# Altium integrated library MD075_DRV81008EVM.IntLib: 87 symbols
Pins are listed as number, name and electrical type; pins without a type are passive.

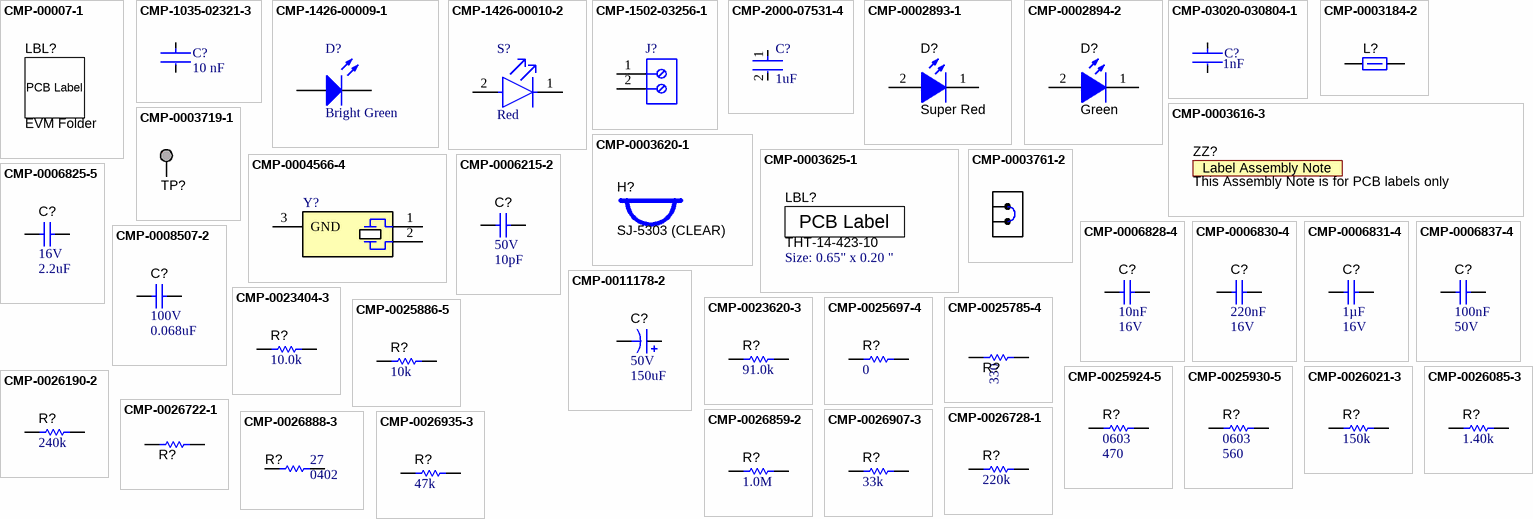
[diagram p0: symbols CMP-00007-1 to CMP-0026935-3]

## CMP-00007-1
designator LBL?, comment EVM Folder
Harsh Environment Multi-Purpose Polyester Labels for 3" Core Printers - 0.375" x 0.375", White; Manufacturer: Brady; PartNumber: THT-14-423-10; CompType: Label; Body Material: PET,Polyester; Note: Size: 0.375" x 0.375"
footprint Label_375x375 (Thermal Transfer Label)

## CMP-1035-02321-3
designator C?, comment value 10 nF  (hidden comment: CC0603KPX7R9BB103)
CAP CER 10000PF 50V X7R 0603; Manufacturer: YAGEO; Alternative PartNumber: 885382206002; Alternative Manufacturer: Wurth Elektronik; Tolerance: 0.1; Material: Ceramic; Temperature Coefficient: 15%
footprint FP-CC0603-DA-MFG
footprint FP-CC0603-DA-IPC_C
footprint FP-CC0603-DA-IPC_B
footprint FP-CC0603-DA-IPC_A
pins: 1, 2

## CMP-1426-00009-1
designator D?, comment Color: Bright Green  (hidden comment: 150080VS75000)
SMD mono-color Chip LED, WL-SMCW, Bright Green; Manufacturer: Wuerth Elektronik
footprint 0805_A (Chip LED, 2-Leads, Body 2.0x1.3mm, IPC Medium Density)
pins: 1 K, 2 A

## CMP-1426-00010-2
designator S?, comment Color: Red  (hidden comment: 150080SS75000)
LED RED CLEAR 0805 SMD; Forward Voltage: 1.9V; Luminous Intensity: 60mcd; Dominant Wavelength: 630nm; Forward Current: 30mA; Viewing Angle: 140°; Lens Color: Colorless; Test Current: 20mA; Lens Size: 1.25mm
footprint FP-150080SS75000-MFG
pins: 1 C, 2 A

## CMP-1502-03256-1
designator J?, comment 691101710002  (value not drawn)
Series 101 - 5.00 mm Horizontal Entry Modular with Pressure Clamp WR-TBL, 2 pin; Manufacturer: Wurth Elektronik; Pin Number: 2; Pitch: 5.00mm
footprint 691101710002 (5,00mm - modular - blue - Horizontal entry with pressure clamp - 12,6mm height - 02p)
pins: 1, 2

## CMP-2000-07531-4
designator C?, comment Capacitance: 1uF  (hidden comment: UMK107AB7105KA-T)
Ceramic Capacitor General Use 1uF ±10% 50V X7R 0603
footprint FP-0603-L_1_6_0_15-W_0_8-IPC_C
footprint FP-0603-L_1_6_0_15-W_0_8-MFG
footprint FP-0603-L_1_6_0_15-W_0_8-IPC_A
footprint FP-0603-L_1_6_0_15-W_0_8-IPC_B
pins: 1, 2

## CMP-0002893-1
designator D?, comment value Super Red  (hidden comment: 150060SS75000)
LED, Super Red, SMD; Manufacturer: Wurth Elektronik; Io_A: 20mA; Value1: W; U/M: EA; Vf_V: 1.9V; Type: AlInGaP
footprint WL-SMCW_RED (WURTH)
pins: 1 K, 2 A

## CMP-0002894-2
designator D?, comment value Green  (hidden comment: 150060VS75000)
LED, Green, SMD; Manufacturer: Wurth Elektronik; Type: AlInGaP; Vf_V: 2V; Io_A: 20mA; Value1: W
footprint WL-SMCW_GREEN (WURTH)
pins: 1 K, 2 A

## CMP-03020-030804-1
designator C?, comment 1nF
CAP CER 1000PF 50V X7R 0603; Manufacturer Part Number: C0603C102J5RACAUTO; Manufacturer: KEMET; Alternate PartNumber: 885012206083; Alternate Manufacturer: Wurth Elektronik; Material: Ceramic; Value: 1,000 pF; Temperature Coefficient: 30ppm/°C; Automotive Grade: Grade 1; Tolerance: 0.05
footprint FP-C0603C-CF-MFG
footprint FP-C0603C-CF-IPC_C
footprint FP-C0603C-CF-IPC_B
footprint FP-C0603C-CF-IPC_A
pins: 1, 2

## CMP-0003184-2
designator L?, comment 742792621  (value not drawn)
Ferrite Bead, 140 ohm @ 100 MHz, 0.55 A, 0603; Manufacturer: Wurth Elektronik; Ztyp@1GHz_Ohm: 271.401; ZTyp@100MHz_Ohm: 140; SizeAreaWB_mm2: 4.68; DCR_ohm: 0.2; Value1: 0.2 ohm; Value: 140 ohm; Imax_A: 550mA; SizeZ_mm: 1; SizeX_mm: 1.6; SizeY_mm: 0.8; Value2: 0.55A; SizeArea_mm2: 1.28
footprint 0603 (0603 from SM-752 data)
footprint 0603_HV (Ernesto recommended land pattern.  26 mil between pads.)
footprint 0603L (0603 from SM-752 data)
footprint 0603S
footprint 0603M (0603 from SM-752 data)
pins: 1, 2

## CMP-0003616-3
designator ZZ?, comment This Assembly Note is for PCB labels only  (no BOM)
Key: AssemblyNoteLabel
footprint AssemblyNoteLabel (Assembly Note for PCB Labels)

## CMP-0003620-1
designator H?, comment SJ-5303 (CLEAR)
Bumpon, Hemisphere, 0.44 X 0.20, Clear; Manufacturer: 3M
footprint Bumpon_SJ5003Transparent (3M Hemispherical Bumpon transparent)

## CMP-0003625-1
designator LBL?, comment THT-14-423-10  Note: Size: 0.65" x 0.20 "
Thermal Transfer Printable Labels, 0.650" W x 0.200" H - 10,000 per roll; Manufacturer: Brady; CompType: Label
footprint Label_650x200 (Thermal Transfer Label)

## CMP-0003719-1
designator TP?, comment TP_H0.45P0.75  (value not drawn)  (no BOM)
Testpoint; Manufacturer: Texas Instruments; CompType: Pad
footprint TP_H045P075 (TP_H0.45P0.75)
pins: 1

## CMP-0003761-2
designator SH-J?, comment 60900213421  (value not drawn)
Shunt, 2.54mm, Gold, Black; Manufacturer: Wurth Elektronik
footprint Wurth_60900213421 (Shunt, 2.54mm, Black)

## CMP-0004566-4
designator Y?, comment MS3V-T1R 32.768KHZ +/-20PPM 12.5PF  (value not drawn)
Crystal, 32.768 kHz, 12.5pF, SMD; Manufacturer: Micro Crystal AG; TaMin_C: -40°C; TaMax_C: 85°C; AEC Category: Q200; AEC Qualified: N; Frequency Tolerance: 20 ppm
footprint XTAL_MS3V-T1R (Micro Crystal Switzerland recommended land pattern)
pins: 1, 2, 3 GND (power)

## CMP-0006215-2
designator C?, comment VDC_V: 50V  ValueDisplayed: 10pF  (hidden comment: 885012005055)
CAP, CERM, 10 pF, 50 V, +/- 5%, C0G/NP0, 0402; Manufacturer: Wurth Elektronik; TaMin_C: -55°C; Polarized: N; SizeAreaWB_mm2: 3; Value1: Unknown; U/M: EA; Value: 10pF; TaMax_C: 125°C; SizeZ_mm: 0.6; SizeX_mm: 1; SizeY_mm: 0.5; Cap_Case: 0402; CompType: Capacitor; AEC Category: Q200
footprint 0402 (0402 from SM-752 data)
footprint 0402S (Based on C0402S footprint from PADS legacy)
footprint 0402L (0402 from SM-752 data)
footprint 0402M (0402 from SM-752 data)
pins: 1, 2

## CMP-0006825-5
designator C?, comment VDC_V: 16V  ValueDisplayed: 2.2uF  (hidden comment: 885012106018)
CAP, CERM, 2.2 uF, 16 V, +/- 20%, X5R, 0603; Manufacturer: Wurth Elektronik; TaMin_C: -55°C; Polarized: N; SizeAreaWB_mm2: 4.68; Value1: Unknown; U/M: EA; Value: 2.2uF; TaMax_C: 85°C; SizeZ_mm: 1; SizeX_mm: 1.6; SizeY_mm: 0.8; Cap_Case: 0603; SizeArea_mm2: 1.28; CompType: Capacitor; Cap_F: 2.2µF; AEC Category: Q200
footprint 0603 (0603 from SM-752 data)
footprint 0603_HV (Ernesto recommended land pattern.  26 mil between pads.)
footprint 0603L (0603 from SM-752 data)
footprint 0603S
footprint 0603M (0603 from SM-752 data)
pins: 1, 2

## CMP-0006828-4
designator C?, comment Cap_F: 10nF  VDC_V: 16V  (hidden comment: 885012206040)
CAP, CERM, 0.01 uF, 16 V, +/- 10%, X7R, 0603; Manufacturer: Wurth Elektronik; TaMin_C: -55°C; Polarized: N; SizeAreaWB_mm2: 4.68; Value1: Unknown; U/M: EA; Value: 0.01uF; TaMax_C: 125°C; SizeZ_mm: 1; SizeX_mm: 1.6; SizeY_mm: 0.8; Cap_Case: 0603; SizeArea_mm2: 1.28; CompType: Capacitor; AEC Category: Q200
footprint 0603 (0603 from SM-752 data)
footprint 0603_HV (Ernesto recommended land pattern.  26 mil between pads.)
footprint 0603L (0603 from SM-752 data)
footprint 0603S
footprint 0603M (0603 from SM-752 data)
pins: 1, 2

## CMP-0006830-4
designator C?, comment Cap_F: 220nF  VDC_V: 16V  (hidden comment: 885012206048)
CAP, CERM, 0.22 uF, 16 V, +/- 10%, X7R, 0603; Manufacturer: Wurth Elektronik; TaMin_C: -55°C; Polarized: N; SizeAreaWB_mm2: 4.68; Value1: Unknown; U/M: EA; Value: 0.22uF; TaMax_C: 125°C; SizeZ_mm: 1; SizeX_mm: 1.6; SizeY_mm: 0.8; Cap_Case: 0603; SizeArea_mm2: 1.28; CompType: Capacitor; AEC Category: Q200
footprint 0603 (0603 from SM-752 data)
footprint 0603_HV (Ernesto recommended land pattern.  26 mil between pads.)
footprint 0603L (0603 from SM-752 data)
footprint 0603S
footprint 0603M (0603 from SM-752 data)
pins: 1, 2

## CMP-0006831-4
designator C?, comment Cap_F: 1µF  VDC_V: 16V  (hidden comment: 885012206052)
CAP, CERM, 1 uF, 16 V, +/- 10%, X7R, 0603; Manufacturer: Wurth Elektronik; TaMin_C: -55°C; Polarized: N; SizeAreaWB_mm2: 4.68; Value1: Unknown; U/M: EA; Value: 1uF; TaMax_C: 125°C; SizeZ_mm: 1; SizeX_mm: 1.6; SizeY_mm: 0.8; Cap_Case: 0603; SizeArea_mm2: 1.28; CompType: Capacitor; AEC Category: Q200
footprint 0603 (0603 from SM-752 data)
footprint 0603_HV (Ernesto recommended land pattern.  26 mil between pads.)
footprint 0603L (0603 from SM-752 data)
footprint 0603S
footprint 0603M (0603 from SM-752 data)
pins: 1, 2

## CMP-0006837-4
designator C?, comment Cap_F: 100nF  VDC_V: 50V  (hidden comment: 885012206095)
CAP, CERM, 0.1 uF, 50 V, +/- 10%, X7R, 0603; Manufacturer: Wurth Elektronik; TaMin_C: -55°C; Polarized: N; SizeAreaWB_mm2: 4.68; Value1: Unknown; U/M: EA; Value: 0.1uF; TaMax_C: 125°C; SizeZ_mm: 1; SizeX_mm: 1.6; SizeY_mm: 0.8; Cap_Case: 0603; SizeArea_mm2: 1.28; CompType: Capacitor; AEC Category: Q200
footprint 0603 (0603 from SM-752 data)
footprint 0603_HV (Ernesto recommended land pattern.  26 mil between pads.)
footprint 0603L (0603 from SM-752 data)
footprint 0603S
footprint 0603M (0603 from SM-752 data)
pins: 1, 2

## CMP-0008507-2
designator C?, comment VDC_V: 100V  ValueDisplayed: 0.068uF  (hidden comment: 12061C683KAT2A)
CAP, CERM, 0.068 uF, 100 V, +/- 10%, X7R, 1206; Manufacturer: AVX; TaMin_C: -55°C; ESR_ohm: 0.045; Polarized: N; SizeAreaWB_mm2: 10.92; Value1: 0.045 ohm; U/M: EA; TaMax_C: 125°C; SizeZ_mm: 1.35; SizeX_mm: 3.2; SizeY_mm: 1.6; Cap_Case: 1206; SizeArea_mm2: 5.12; CompType: Capacitor; Cap_F: 68nF; AEC Category: Q200
footprint 1206 (1206 from SM-752 data)
footprint 1206L (1206 from SM-752 data)
footprint 1206M (1206 from SM-752 data)
pins: 1, 2

## CMP-0011178-2
designator C?, comment VDC_V: 50V  ValueDisplayed: 150uF  (hidden comment: EEE-FK1H151P)
CAP, AL, 150 uF, 50 V, +/- 20%, 0.18 ohm, AEC-Q200 Grade 2, SMD; Manufacturer: Panasonic; Alternate Manufacturer: Wurth Elektronik; Alternate PartNumber: 865080657017; TaMin_C: -55°C; ESR_ohm: 0.18; Polarized: Y; SizeAreaWB_mm2: 172.2; U/M: EA; Value: 150uF; TaMax_C: 105°C; SizeZ_mm: 10.2; SizeX_mm: 12; SizeY_mm: 10.3; Cap_Case: G; SizeArea_mm2: 123.6; CompType: Capacitor; Cap_F: 150µF; IRMS_A: 670mA; AEC Grade: 2; AEC Category: Q200
footprint SM_RADIAL_G (10 x 10.2mm:  Panasonic G)
pins: 1 +, 2 -

## CMP-0023404-3
designator R?, comment ValueDisplayed: 10.0k  (hidden comment: RG1608P-103-B-T5)
RES, 10.0 k, 0.1%, 0.1 W, 0603; Manufacturer: Susumu Co Ltd; Power_W: 100mW; TempCo: 25 ppm/C; Value_Code: 10k0; U/M: EA; Value: 10.0k; EIA_Code: E192; Res_ohm: 10k; SizeX_mm: 1.6; SizeY_mm: 0.8; SizeZ_mm: 1; Value2: 0.1W; SizeArea_mm2: 1.28; CompType: Resistor; VDC_V: 75V; AEC Category: Q200
footprint 0603 (0603 from SM-752 data)
footprint 0603_HV (Ernesto recommended land pattern.  26 mil between pads.)
footprint 0603L (0603 from SM-752 data)
footprint 0603S
footprint 0603M (0603 from SM-752 data)
pins: 1, 2

## CMP-0023620-3
designator R?, comment ValueDisplayed: 91.0k  (hidden comment: RG1608P-913-B-T5)
RES, 91.0 k, 0.1%, 0.1 W, 0603; Manufacturer: Susumu Co Ltd; Power_W: 100mW; TempCo: 25 ppm/C; Value_Code: 91k0; U/M: EA; Value: 91.0k; Res_ohm: 91k; SizeX_mm: 1.6; SizeY_mm: 0.8; SizeZ_mm: 1; Value2: 0.1W; SizeArea_mm2: 1.28; CompType: Resistor; VDC_V: 75V; AEC Category: Q200
footprint 0603 (0603 from SM-752 data)
footprint 0603_HV (Ernesto recommended land pattern.  26 mil between pads.)
footprint 0603L (0603 from SM-752 data)
footprint 0603S
footprint 0603M (0603 from SM-752 data)
pins: 1, 2

## CMP-0025697-4
designator R?, comment value 0  (hidden comment: Resistor)
RES, 0, 5%, 0.1 W, AEC-Q200 Grade 0, 0603; PartNumber: CRCW06030000Z0EA; Manufacturer: Vishay-Dale; Value_Code: 0000; Power_W: 100mW; Value2: 0.1W; VDC_V: 75V; TempCo: 200 ppm/C; EIA_Code: E24; AEC Category: Q200; AEC Qualified: Y; SizeArea_mm2: 1.28; SizeX_mm: 1.6; SizeY_mm: 0.8; SizeZ_mm: 1
footprint 0603 (0603 from SM-752 data)
footprint 0603_HV (Ernesto recommended land pattern.  26 mil between pads.)
footprint 0603L (0603 from SM-752 data)
footprint 0603S
footprint 0603M (0603 from SM-752 data)
pins: 1, 2

## CMP-0025785-4
designator R?, comment ValueDisplayed: 330  (hidden comment: Resistor)
RES, 330, 5%, 0.1 W, AEC-Q200 Grade 0, 0603; PartNumber: CRCW0603330RJNEA; Manufacturer: Vishay-Dale; Value: 330; Value_Code: 330R; Power_W: 100mW; Value2: 0.1W; VDC_V: 75V; TempCo: 200 ppm/C; EIA_Code: E24; AEC Category: Q200; AEC Qualified: Y; AEC Grade: 0; SizeX_mm: 1.6; SizeY_mm: 0.8; SizeZ_mm: 1; SizeArea_mm2: 1.28
footprint 0603 (0603 from SM-752 data)
footprint 0603_HV (Ernesto recommended land pattern.  26 mil between pads.)
footprint 0603L (0603 from SM-752 data)
footprint 0603S
footprint 0603M (0603 from SM-752 data)
pins: 1, 2

## CMP-0025886-5
designator R?, comment ValueDisplayed: 10k  (hidden comment: RC0603JR-0710KL)
RES, 10 k, 5%, 0.1 W, 0603; Manufacturer: Yageo; Power_W: 100mW; TempCo: 100 ppm/C; Value_Code: 10k0; Value: 10k; EIA_Code: E24; SizeX_mm: 1.6; SizeY_mm: 0.8; SizeZ_mm: 1; Value2: 0.1W; SizeArea_mm2: 1.28; CompType: Resistor; AEC Qualified: N; VDC_V: 75V; AEC Category: Q200; SizeAreaWB_mm2: 4.68
footprint 0603 (0603 from SM-752 data)
footprint 0603_HV (Ernesto recommended land pattern.  26 mil between pads.)
footprint 0603L (0603 from SM-752 data)
footprint 0603S
footprint 0603M (0603 from SM-752 data)
pins: 1, 2

## CMP-0025924-5
designator R?, comment PackageReference: 0603  ValueDisplayed: 470  (hidden comment: RC0603JR-07470RL)
RES, 470, 5%, 0.1 W, 0603; Manufacturer: Yageo; Power_W: 100mW; TempCo: 100 ppm/C; Value_Code: 470R; Value: 470; EIA_Code: E24; SizeX_mm: 1.6; SizeY_mm: 0.8; SizeZ_mm: 1; Value2: 0.1W; SizeArea_mm2: 1.28; CompType: Resistor; AEC Qualified: N; VDC_V: 75V; AEC Category: Q200; SizeAreaWB_mm2: 4.68
footprint 0603 (0603 from SM-752 data)
footprint 0603_HV (Ernesto recommended land pattern.  26 mil between pads.)
footprint 0603L (0603 from SM-752 data)
footprint 0603S
footprint 0603M (0603 from SM-752 data)
pins: 1, 2

## CMP-0025930-5
designator R?, comment PackageReference: 0603  ValueDisplayed: 560  (hidden comment: RC0603JR-07560RL)
RES, 560, 5%, 0.1 W, 0603; Manufacturer: Yageo; Power_W: 100mW; TempCo: 100 ppm/C; Value_Code: 560R; Value: 560; EIA_Code: E24; SizeX_mm: 1.6; SizeY_mm: 0.8; SizeZ_mm: 1; Value2: 0.1W; SizeArea_mm2: 1.28; CompType: Resistor; AEC Qualified: N; VDC_V: 75V; AEC Category: Q200; SizeAreaWB_mm2: 4.68
footprint 0603 (0603 from SM-752 data)
footprint 0603_HV (Ernesto recommended land pattern.  26 mil between pads.)
footprint 0603L (0603 from SM-752 data)
footprint 0603S
footprint 0603M (0603 from SM-752 data)
pins: 1, 2

## CMP-0026021-3
designator R?, comment ValueDisplayed: 150k  (hidden comment: CRCW0402150KFKED)
RES, 150 k, 1%, 0.063 W, AEC-Q200 Grade 0, 0402; Manufacturer: Vishay-Dale; Power_W: 63mW; TempCo: 100 ppm/C; Value: 150k; EIA_Code: E96; SizeX_mm: 1; SizeY_mm: 0.5; SizeZ_mm: 0.6; Value2: 0.063W; CompType: Resistor; AEC Qualified: Y; VDC_V: 50V; AEC Category: Q200; AEC Grade: 0
footprint 0402 (0402 from SM-752 data)
footprint 0402S (Based on C0402S footprint from PADS legacy)
footprint 0402L (0402 from SM-752 data)
footprint 0402M (0402 from SM-752 data)
pins: 1, 2

## CMP-0026085-3
designator R?, comment ValueDisplayed: 1.40k  (hidden comment: CRCW04021K40FKED)
RES, 1.40 k, 1%, 0.063 W, AEC-Q200 Grade 0, 0402; Manufacturer: Vishay-Dale; Power_W: 63mW; TempCo: 100 ppm/C; Value_Code: 1k40; Value: 1.40k; EIA_Code: E96; Res_ohm: 1.4k; SizeX_mm: 1; SizeY_mm: 0.5; SizeZ_mm: 0.6; Value2: 0.063W; CompType: Resistor; AEC Qualified: Y; VDC_V: 50V; AEC Category: Q200; AEC Grade: 0
footprint 0402 (0402 from SM-752 data)
footprint 0402S (Based on C0402S footprint from PADS legacy)
footprint 0402L (0402 from SM-752 data)
footprint 0402M (0402 from SM-752 data)
pins: 1, 2

## CMP-0026190-2
designator R?, comment ValueDisplayed: 240k  (hidden comment: CRCW0402240KFKED)
RES, 240 k, 1%, 0.063 W, AEC-Q200 Grade 0, 0402; Manufacturer: Vishay-Dale; Power_W: 63mW; TempCo: 100 ppm/C; Value: 240k; SizeX_mm: 1; SizeY_mm: 0.5; SizeZ_mm: 0.6; Value2: 0.063W; CompType: Resistor; AEC Qualified: Y; VDC_V: 50V; AEC Category: Q200; AEC Grade: 0
footprint 0402 (0402 from SM-752 data)
footprint 0402S (Based on C0402S footprint from PADS legacy)
footprint 0402L (0402 from SM-752 data)
footprint 0402M (0402 from SM-752 data)
pins: 1, 2

## CMP-0026722-1
designator R?, comment RC0402FR-07100RL  (value not drawn)
RES, 100, 1%, 0.063 W, 0402; Manufacturer: Yageo America; Power_W: 63mW; TempCo: 100 ppm/C; Value_Code: 100R; U/M: EA; Value: 100; EIA_Code: E96; SizeX_mm: 1; SizeY_mm: 0.5; SizeZ_mm: 0.6; Value2: 0.063W; CompType: Resistor; AEC Qualified: N; VDC_V: 50V; AEC Category: Q200
footprint 0402 (0402 from SM-752 data)
footprint 0402S (Based on C0402S footprint from PADS legacy)
footprint 0402L (0402 from SM-752 data)
footprint 0402M (0402 from SM-752 data)
pins: 1, 2

## CMP-0026728-1
designator R?, comment ValueDisplayed: 220k  (hidden comment: RC0402FR-07220KL)
RES, 220 k, 1%, 0.0625 W, 0402; Manufacturer: Yageo America; Power_W: 62.5mW; TempCo: 100 ppm/C; U/M: EA; Value: 220k; SizeX_mm: 1; SizeY_mm: 0.5; SizeZ_mm: 0.6; CompType: Resistor; AEC Qualified: N; VDC_V: 50V; AEC Category: Q200
footprint 0402 (0402 from SM-752 data)
footprint 0402S (Based on C0402S footprint from PADS legacy)
footprint 0402L (0402 from SM-752 data)
footprint 0402M (0402 from SM-752 data)
pins: 1, 2

## CMP-0026859-2
designator R?, comment ValueDisplayed: 1.0M  (hidden comment: CRCW04021M00JNED)
RES, 1.0 M, 5%, 0.063 W, AEC-Q200 Grade 0, 0402; Manufacturer: Vishay-Dale; Power_W: 63mW; TempCo: 200 ppm/C; Value_Code: 1M00; Value: 1.0Meg; EIA_Code: E24; Res_ohm: 1M; SizeX_mm: 1; SizeY_mm: 0.5; SizeZ_mm: 0.6; Value2: 0.063W; CompType: Resistor; AEC Qualified: Y; VDC_V: 50V; AEC Category: Q200; AEC Grade: 0
footprint 0402 (0402 from SM-752 data)
footprint 0402S (Based on C0402S footprint from PADS legacy)
footprint 0402L (0402 from SM-752 data)
footprint 0402M (0402 from SM-752 data)
pins: 1, 2

## CMP-0026888-3
designator R?, comment PackageReference: 0402  ValueDisplayed: 27  (hidden comment: CRCW040227R0JNED)
RES, 27, 5%, 0.063 W, AEC-Q200 Grade 0, 0402; Manufacturer: Vishay-Dale; Power_W: 63mW; TempCo: 200 ppm/C; Value_Code: 27R0; Value: 27; EIA_Code: E24; SizeX_mm: 1; SizeY_mm: 0.5; SizeZ_mm: 0.6; Value2: 0.063W; CompType: Resistor; AEC Qualified: Y; VDC_V: 50V; AEC Category: Q200; AEC Grade: 0
footprint 0402 (0402 from SM-752 data)
footprint 0402S (Based on C0402S footprint from PADS legacy)
footprint 0402L (0402 from SM-752 data)
footprint 0402M (0402 from SM-752 data)
pins: 1, 2

## CMP-0026907-3
designator R?, comment ValueDisplayed: 33k  (hidden comment: CRCW040233K0JNED)
RES, 33 k, 5%, 0.063 W, AEC-Q200 Grade 0, 0402; Manufacturer: Vishay-Dale; Power_W: 63mW; TempCo: 200 ppm/C; Value_Code: 33k0; Value: 33k; EIA_Code: E24; SizeX_mm: 1; SizeY_mm: 0.5; SizeZ_mm: 0.6; Value2: 0.063W; CompType: Resistor; AEC Qualified: Y; VDC_V: 50V; AEC Category: Q200; AEC Grade: 0
footprint 0402 (0402 from SM-752 data)
footprint 0402S (Based on C0402S footprint from PADS legacy)
footprint 0402L (0402 from SM-752 data)
footprint 0402M (0402 from SM-752 data)
pins: 1, 2

## CMP-0026935-3
designator R?, comment ValueDisplayed: 47k  (hidden comment: CRCW040247K0JNED)
RES, 47 k, 5%, 0.063 W, AEC-Q200 Grade 0, 0402; Manufacturer: Vishay-Dale; Power_W: 63mW; TempCo: 200 ppm/C; Value_Code: 47k0; Value: 47k; EIA_Code: E24; SizeX_mm: 1; SizeY_mm: 0.5; SizeZ_mm: 0.6; Value2: 0.063W; CompType: Resistor; AEC Qualified: Y; VDC_V: 50V; AEC Category: Q200; AEC Grade: 0
footprint 0402 (0402 from SM-752 data)
footprint 0402S (Based on C0402S footprint from PADS legacy)
footprint 0402L (0402 from SM-752 data)
footprint 0402M (0402 from SM-752 data)
pins: 1, 2

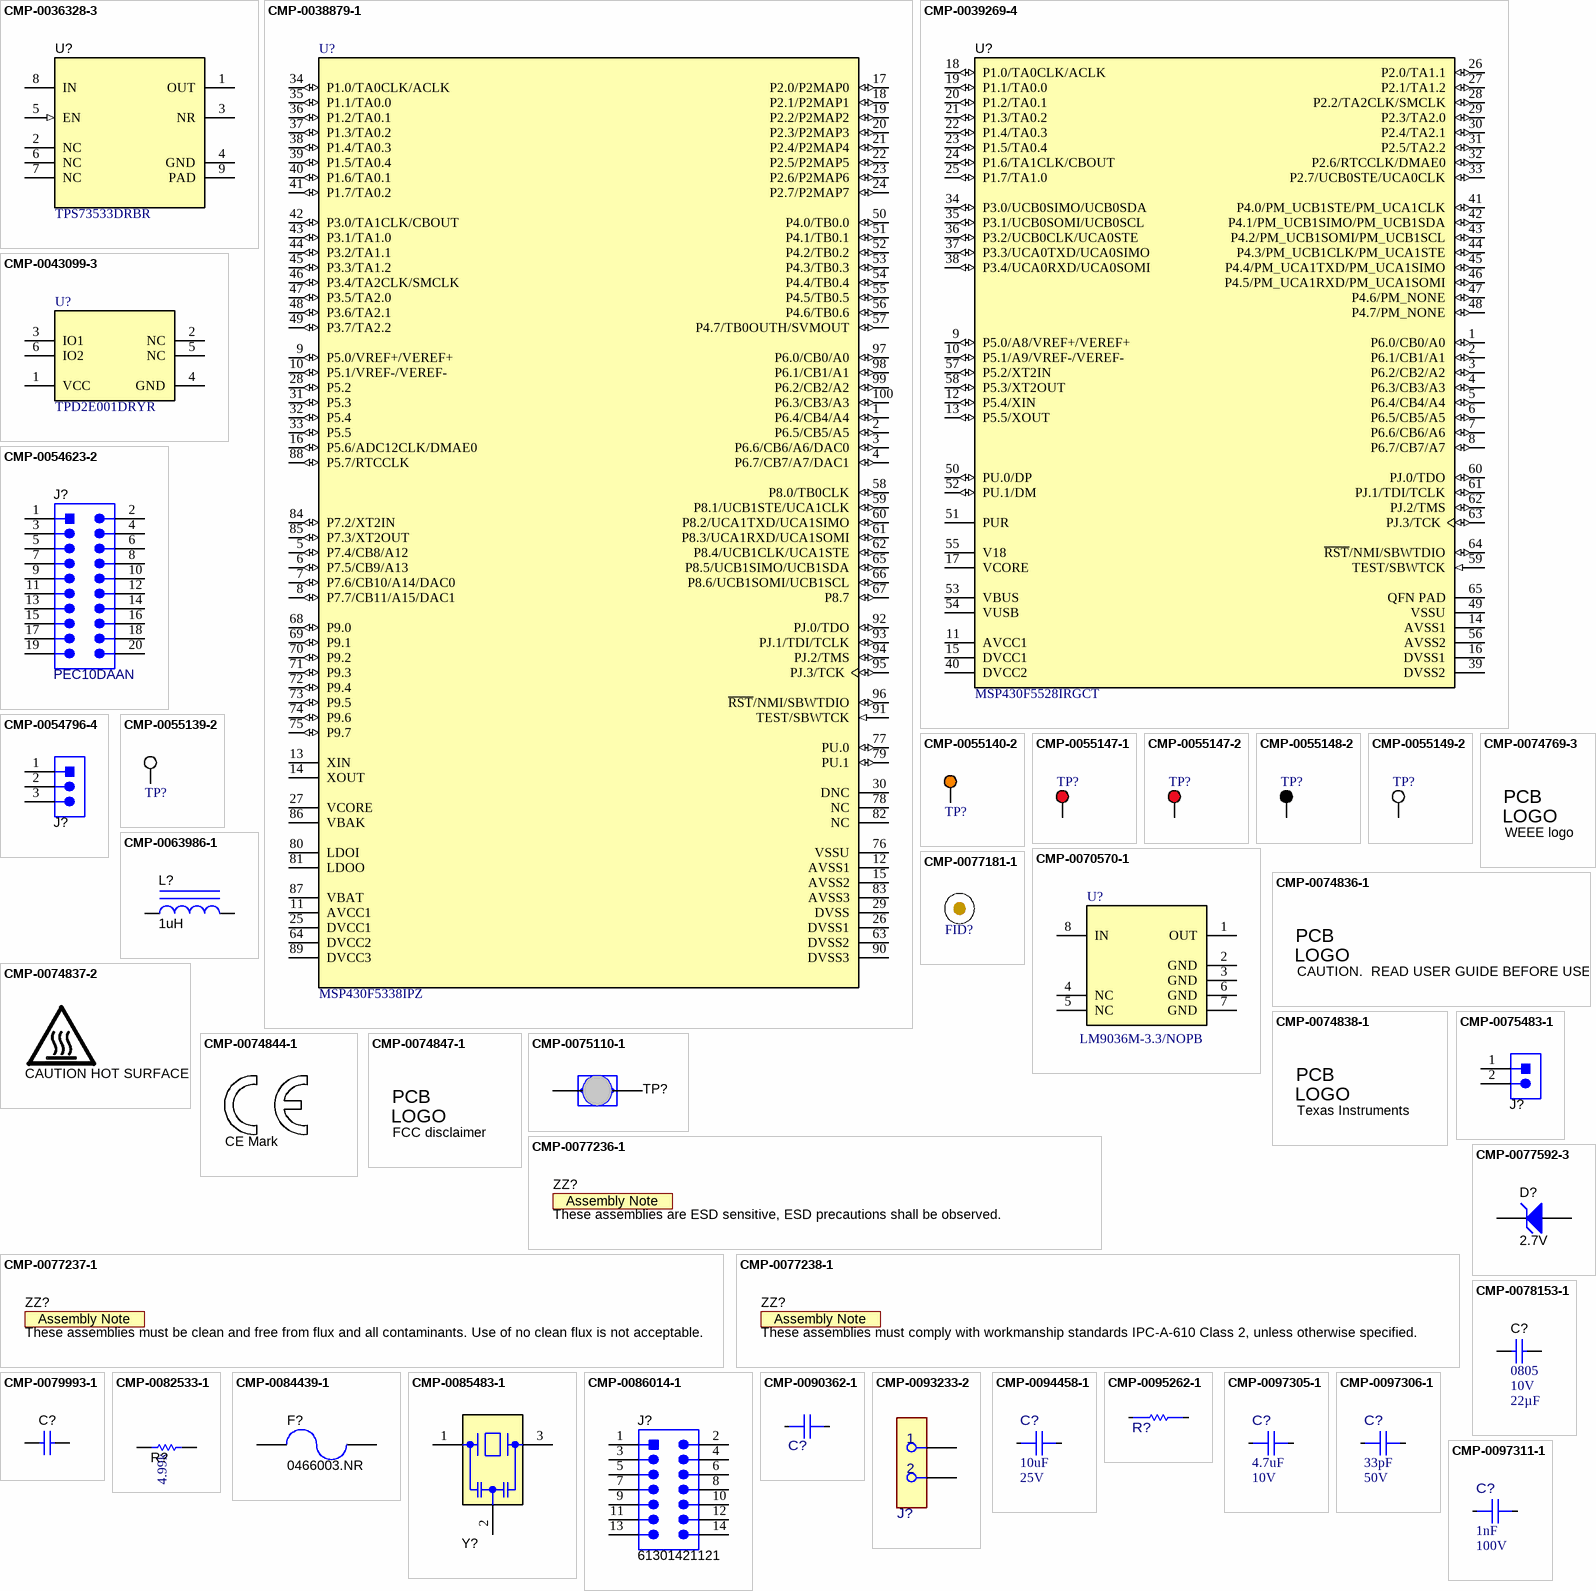
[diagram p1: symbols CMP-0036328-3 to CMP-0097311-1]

## CMP-0036328-3
designator U?, comment TPS73533DRBR
500mA, Adjustable, Low Quiescent Current, Low-Noise, High-PSRR, Single-Output LDO Regulator, DRB0008A (VSON-8); Manufacturer: Texas Instruments; CompType: IC; Green_Lifecycle: Active; SizeZ_mm: 1.0; Iq(Typ)(mA): 0.04; SizeY_mm: 3.0; SizeAreaWB_mm2: 16.0; SizeArea_mm2: 9.0; AEC Category: Q200; Vout Adj(Max)(V): 3.3; AEC Qualified: N; Accuracy(%): 2; Vin(Max)(V): 6.5; Vdo(Typ)(mV): 280; Iout(Max)(A): 0.5; Green_REACh: Passed; Rating: Catalog; Vin(Min)(V): 2.7
footprint DRB0008A (VSON-8)
footprint DRB0008A_NV (VSON-8)
pins: 1 OUT (power), 2 NC, 3 NR, 4 GND (power), 5 EN (in), 6 NC, 7 NC, 8 IN (power), 9 PAD (power)

## CMP-0038879-1
designator U?, comment MSP430F5338IPZ
20 MHz Mixed Signal Microcontroller with 256 KB Flash, 18432 B SRAM and 74 GPIOs, -40 to 85 degC, 100-pin QFP (PZ), Green (RoHS & no Sb/Br); Manufacturer: Texas Instruments; Flash(KB): 256; USCI_B (I2C & SPI): 2; ADC Channels: 16; Comparators: Yes; Frequency(MHz): 20; DMA: 3; SRAM(B): 18432; Multiplier: 32x32; GPIO: 74; Timers - 16-bit: 4; SubFamily: 5 Series; ADC: 12-bit SAR
footprint PZT0100A_N (QFP, 100-Leads, Body 14x14mm, Pitch 0.50mm, IPC Medium Density)
footprint PZT0100A_M (QFP, 100-Leads, Body 14x14mm, Pitch 0.50mm, IPC Low Density)
footprint PZT0100A_L (QFP, 100-Leads, Body 14x14mm, Pitch 0.50mm, IPC High Density)
pins: 1 P6.4/CB4/A4 (io), 2 P6.5/CB5/A5 (io), 3 P6.6/CB6/A6/DAC0 (io), 4 P6.7/CB7/A7/DAC1 (io), 5 P7.4/CB8/A12 (io), 6 P7.5/CB9/A13 (io), 7 P7.6/CB10/A14/DAC0 (io), 8 P7.7/CB11/A15/DAC1 (io), 9 P5.0/VREF+/VEREF+ (io), 10 P5.1/VREF-/VEREF- (io), 11 AVCC1 (power) "Analog power supply", 12 AVSS1 (power) "Analog ground supply", 13 XIN "Input terminal for crystal oscillator XT1", 14 XOUT "Output terminal of crystal oscillator XT1", 15 AVSS2 (power) "Analog ground supply", 16 P5.6/ADC12CLK/DMAE0 (io), 17 P2.0/P2MAP0 (io), 18 P2.1/P2MAP1 (io), 19 P2.2/P2MAP2 (io), 20 P2.3/P2MAP3 (io), 21 P2.4/P2MAP4 (io), 22 P2.5/P2MAP5 (io), 23 P2.6/P2MAP6 (io), 24 P2.7/P2MAP7 (io), 25 DVCC1 (power) "Digital power supply", 26 DVSS1 (power) "Digital ground supply", 27 VCORE "Regulated core power supply (internal use only, no external current loading)", 28 P5.2 (io) "General-purpose digital I/O", 29 DVSS (power) "Digital ground supply", 30 DNC "Do not connect. It is strongly recommended to leave this terminal open.", 31 P5.3 (io) "General-purpose digital I/O", 32 P5.4 (io) "General-purpose digital I/O", 33 P5.5 (io) "General-purpose digital I/O", 34 P1.0/TA0CLK/ACLK (io), 35 P1.1/TA0.0 (io), 36 P1.2/TA0.1 (io), 37 P1.3/TA0.2 (io), 38 P1.4/TA0.3 (io), 39 P1.5/TA0.4 (io), 40 P1.6/TA0.1 (io), 41 P1.7/TA0.2 (io), 42 P3.0/TA1CLK/CBOUT (io), 43 P3.1/TA1.0 (io), 44 P3.2/TA1.1 (io), 45 P3.3/TA1.2 (io), 46 P3.4/TA2CLK/SMCLK (io), 47 P3.5/TA2.0 (io), 48 P3.6/TA2.1 (io), 49 P3.7/TA2.2 (io), 50 P4.0/TB0.0 (io), 51 P4.1/TB0.1 (io), 52 P4.2/TB0.2 (io), 53 P4.3/TB0.3 (io), 54 P4.4/TB0.4 (io), 55 P4.5/TB0.5 (io), 56 P4.6/TB0.6 (io), 57 P4.7/TB0OUTH/SVMOUT (io), 58 P8.0/TB0CLK (io), 59 P8.1/UCB1STE/UCA1CLK (io), 60 P8.2/UCA1TXD/UCA1SIMO (io), 61 P8.3/UCA1RXD/UCA1SOMI (io), 62 P8.4/UCB1CLK/UCA1STE (io), 63 DVSS2 (power) "Digital ground supply", 64 DVCC2 (power) "Digital power supply", 65 P8.5/UCB1SIMO/UCB1SDA (io), 66 P8.6/UCB1SOMI/UCB1SCL (io), 67 P8.7 (io) "General-purpose digital I/O", 68 P9.0 (io) "General-purpose digital I/O", 69 P9.1 (io) "General-purpose digital I/O", 70 P9.2 (io) "General-purpose digital I/O", 71 P9.3 (io) "General-purpose digital I/O", 72 P9.4 (io) "General-purpose digital I/O", 73 P9.5 (io) "General-purpose digital I/O", 74 P9.6 (io) "General-purpose digital I/O", 75 P9.7 (io) "General-purpose digital I/O", 76 VSSU (power) "PU ground supply", 77 PU.0 (io) "General-purpose digital I/O - controlled by PU control register", 78 NC "No connect.", 79 PU.1 (io) "General-purpose digital I/O - controlled by PU control register", 80 LDOI (power) "LDO input", 81 LDOO (power) "LDO output", 82 NC "No connect.", 83 AVSS3 (power) "Analog ground supply", 84 P7.2/XT2IN (io), 85 P7.3/XT2OUT (io), 86 VBAK "Capacitor for backup subsystem. Do not load this pin externally. For capacitor values, see CBAK in Recommended Operating Conditions.", 87 VBAT (power) "Backup or secondary supply voltage. If backup voltage is not supplied, connect to DVCC externally.", 88 P5.7/RTCCLK (io) "General-purpose digital I/O RTCCLK output", 89 DVCC3 (power) "Digital power supply", 90 DVSS3 (power) "Digital ground supply", 91 TEST/SBWTCK (in), 92 PJ.0/TDO (io), 93 PJ.1/TDI/TCLK (io), 94 PJ.2/TMS (io), 95 PJ.3/TCK (io), 96 ~{RST}/NMI/SBWTDIO (io), 97 P6.0/CB0/A0 (io), 98 P6.1/CB1/A1 (io), 99 P6.2/CB2/A2 (io), 100 P6.3/CB3/A3 (io)

## CMP-0039269-4
designator U?, comment MSP430F5528IRGCT
16-Bit Ultra-Low-Power Microcontroller, 128KB Flash, 8KB RAM, USB, 12Bit ADC, 2 USCIs, 32Bit HW MPY, RGC0064B (VQFN-64); Alternate Manufacturer: Texas Instruments; Alternate PartNumber: MSP430F5528IRGCR; ADC: 12-bit SAR; ADC Channels: 16; Brown Out Reset: Yes; DMA: 3; Flash(KB): 128; Frequency(MHz): 25; GPIO: 47; Multiplier: 32x32; SRAM(B): 8192; Timers - 16-bit: 4; USB: 1; USCI_A (UART/LIN/IrDA/SPI): 2; Rating: Catalog; SizeArea_mm2: 81.0; SizeZ_mm: 1.0; Green_REACh: Passed; AEC Qualified: N; AEC Category: Q200; CompType: IC; Green_Lifecycle: Active; SizeY_mm: 9.0; SizeAreaWB_mm2: 121.0
footprint RGC0064B (VQFN-64)
footprint RGC0064B_NV (VQFN-64)
pins: 1 P6.0/CB0/A0 (io), 2 P6.1/CB1/A1 (io), 3 P6.2/CB2/A2 (io), 4 P6.3/CB3/A3 (io), 5 P6.4/CB4/A4 (io), 6 P6.5/CB5/A5 (io), 7 P6.6/CB6/A6 (io), 8 P6.7/CB7/A7 (io), 9 P5.0/A8/VREF+/VEREF+ (io), 10 P5.1/A9/VREF-/VEREF- (io), 11 AVCC1 (power) "Analog power supply", 12 P5.4/XIN (io), 13 P5.5/XOUT (io), 14 AVSS1 (power) "Analog ground supply", 15 DVCC1 (power) "Digital power supply", 16 DVSS1 (power) "Digital ground supply", 17 VCORE "Regulated core power supply output (internal use only, no external current loading)", 18 P1.0/TA0CLK/ACLK (io), 19 P1.1/TA0.0 (io), 20 P1.2/TA0.1 (io), 21 P1.3/TA0.2 (io), 22 P1.4/TA0.3 (io), 23 P1.5/TA0.4 (io), 24 P1.6/TA1CLK/CBOUT (io), 25 P1.7/TA1.0 (io), 26 P2.0/TA1.1 (io), 27 P2.1/TA1.2 (io), 28 P2.2/TA2CLK/SMCLK (io), 29 P2.3/TA2.0 (io), 30 P2.4/TA2.1 (io), 31 P2.5/TA2.2 (io), 32 P2.6/RTCCLK/DMAE0 (io), 33 P2.7/UCB0STE/UCA0CLK (io), 34 P3.0/UCB0SIMO/UCB0SDA (io), 35 P3.1/UCB0SOMI/UCB0SCL (io), 36 P3.2/UCB0CLK/UCA0STE (io), 37 P3.3/UCA0TXD/UCA0SIMO (io), 38 P3.4/UCA0RXD/UCA0SOMI (io), 39 DVSS2 (power) "Digital ground supply", 40 DVCC2 (power) "Digital power supply", 41 P4.0/PM_UCB1STE/PM_UCA1CLK (io), 42 P4.1/PM_UCB1SIMO/PM_UCB1SDA (io), 43 P4.2/PM_UCB1SOMI/PM_UCB1SCL (io), 44 P4.3/PM_UCB1CLK/PM_UCA1STE (io), 45 P4.4/PM_UCA1TXD/PM_UCA1SIMO (io), 46 P4.5/PM_UCA1RXD/PM_UCA1SOMI (io), 47 P4.6/PM_NONE (io), 48 P4.7/PM_NONE (io), 49 VSSU (power) "USB PHY ground supply", 50 PU.0/DP (io), 51 PUR "USB pullup resistor pin (open drain). The voltage level at the PUR pin is used to invoke the default USB BSL. Recommended 1-Mohm resistor to ground. See USB BSL for more information.", 52 PU.1/DM (io), 53 VBUS (power) "USB LDO input (connect to USB power source)", 54 VUSB (power) "USB LDO output", 55 V18 "USB regulated power (internal use only, no external current loading)", 56 AVSS2 (power) "Analog ground supply", 57 P5.2/XT2IN (io), 58 P5.3/XT2OUT (io), 59 TEST/SBWTCK (in), 60 PJ.0/TDO (io), 61 PJ.1/TDI/TCLK (io), 62 PJ.2/TMS (io), 63 PJ.3/TCK (io), 64 ~{RST}/NMI/SBWTDIO (io), 65 QFN PAD (power) "QFN package pad connection to VSS recommended."
1 alternate drawing of the same symbol

## CMP-0043099-3
designator U?, comment TPD2E001DRYR
Low-Capacitance 2-Channel +/-15kV ESD Protection Array for High-Speed Data Interfaces, DRY0006A (USON-6); Manufacturer: Texas Instruments; IO Leakage Current(nA): 1; IEC 61000-4-2 Air-Gap(+/- kV): 15; USB High Speed: TRUE; IO Capacitance(Typ)(pF): 1.5; Eco-Plan: Green (RoHS & no Sb/Br); Breakdown Voltage(Min)(V): 11; IEC 61000-4-2 Contact(+/- kV): 8; AEC Category: Q200; AEC Qualified: N; CompType: IC; SizeAreaWB_mm2: 4.9; SizeArea_mm2: 1.45; SizeX_mm: 1.0; SizeZ_mm: 0.6; Rating: Catalog
footprint DRY0006A (USON-6)
pins: 1 VCC (power) "Power-supply input. Bypass VCC to GND with a 0.1-uF ceramic capacitor.", 2 NC "No connection. Not internally connected.", 3 IO1 "ESD-protected channel", 4 GND (power) "Ground", 5 NC "No connection. Not internally connected.", 6 IO2 "ESD-protected channel"

## CMP-0054623-2
designator J?, comment PEC10DAAN
Header, 2.54mm, 10x2, Tin, TH; Manufacturer: Sullins Connector Solutions; Current_A: 3A; Green_Lifecycle: Not Set; Shrouded: N; Gender: Male; Green_REACh: Incomplete; Row_Count: 2; RowSpacing_mm: 2.54; Cert_UL: Y
footprint SULLINS_PEC10DAAN (SULLINS)
pins: 1, 2, 3, 4, 5, 6, 7, 8, 9, 10, 11, 12, 13, 14, 15, 16, 17, 18, 19, 20
1 alternate drawing of the same symbol

## CMP-0054796-4
designator J?, comment 61300311121  (value not drawn)
Header, 2.54 mm, 3x1, Gold, TH; Manufacturer: Wurth Elektronik; Green_Lifecycle: Active; Green_REACh: Passed; CT: FALSE; CNHeader: TRUE
footprint WURTH_61300311121 (Header, 2.54mm, 3x1, TH)
pins: 1, 2, 3
3 alternate drawings of the same symbol

## CMP-0055139-2
designator TP?, comment 5002  (value not drawn)
Test Point, Miniature, White, TH; Manufacturer: Keystone Electronics; ContactFinish: Silver; Green_REACh: Passed; CT: TRUE; Green_Lifecycle: Active; CNHeader: FALSE
footprint Keystone5002 (For Keystone 500x miniature loop terminals)
pins: 1

## CMP-0055140-2
designator TP?, comment 5003  (value not drawn)
Test Point, Miniature, Orange, TH; Manufacturer: Keystone Electronics; CNHeader: FALSE; Green_Lifecycle: Active; Green_REACh: Passed; ContactFinish: Silver; CT: TRUE
footprint Keystone5003 (For Keystone 500x miniature loop terminals)
pins: 1

## CMP-0055147-1
designator TP?, comment 5010  (value not drawn)
Test Point, Multipurpose, Red, TH; Manufacturer: Keystone; CNHeader: FALSE; Green_Lifecycle: Active; Green_REACh: Passed; ContactFinish: Silver; CT: TRUE
footprint Keystone5010 (Keystone Multipurpose loops)
pins: 1

## CMP-0055147-2
designator TP?, comment 5010  (value not drawn)
Test Point, Multipurpose, Red, TH; Manufacturer: Keystone Electronics; CNHeader: FALSE; Green_Lifecycle: Active; Green_REACh: Passed; ContactFinish: Silver; CT: TRUE
footprint Keystone5010 (Keystone Multipurpose loops)
pins: 1

## CMP-0055148-2
designator TP?, comment 5011  (value not drawn)
Test Point, Multipurpose, Black, TH; Manufacturer: Keystone Electronics; CNHeader: FALSE; Green_Lifecycle: Active; Green_REACh: Passed; ContactFinish: Silver; CT: TRUE
footprint Keystone5011 (Keystone Multipurpose loops)
pins: 1

## CMP-0055149-2
designator TP?, comment 5012  (value not drawn)
Test Point, Multipurpose, White, TH; Manufacturer: Keystone Electronics; ContactFinish: Silver; CT: TRUE; CNHeader: FALSE; Green_Lifecycle: Active; Green_REACh: Passed
footprint Keystone5012 (Keystone Multipurpose loops)
pins: 1

## CMP-0063986-1
designator L?, comment ValueDisplayed: 1uH  (hidden comment: 7443320100)
Inductor, Shielded Drum Core, Ferrite, 1 uH, 24 A, 0.0012 ohm, SMD; Manufacturer: Wurth Elektronik; Isat: 32A @ 30% inductance drop; Irms: 24A @ 50C rise; Green_Lifecycle: Active; SizeAreaWB_mm2: 188.94; DCR_ohm: 1.2m; Green_REACh: Passed; Value: 1uH; Imax_A: 24A; SizeZ_mm: 10; SizeX_mm: 12.1; SizeY_mm: 11.4; SizeArea_mm2: 137.94; Ind_H: 1µH; AEC Category: Q200
footprint WE-HCC_1210 (WURTH)
pins: 1, 2

## CMP-0070570-1
designator U?, comment LM9036M-3.3/NOPB
Ultra-Low Quiescent Current Voltage Regulator, 8-pin Narrow SOIC, Pb-Free; Manufacturer: Texas Instruments; PackageTopMarking: NSZXTT*LM903*6M-3; PowerWise: N; CompType: LDO IC
footprint D0008A_N (SOIC, 8-Leads, Body 4.9x3.9mm, Pitch 1.27mm, IPC Medium Density)
footprint D0008A_M (SOIC, 8-Leads, Body 4.9x3.9mm, Pitch 1.27mm, IPC Low Density)
footprint D0008A_L (SOIC, 8-Leads, Body 4.9x3.9mm, Pitch 1.27mm, IPC High Density)
pins: 1 OUT (power), 2 GND (power), 3 GND (power), 4 NC, 5 NC, 6 GND (power), 7 GND (power), 8 IN (power)

## CMP-0074769-3
designator Logo?, comment WEEE logo  (no BOM)
Manufacturer: Texas Instruments; CompType: IC; AEC Category: Q200
footprint WEEE_Minimum (WEEElie bin)

## CMP-0074836-1
designator Logo?, comment CAUTION.  READ USER GUIDE BEFORE USE  (no BOM)
IEC 61010-1 Caution Warning; Library Reference: Logo; SymbolCreator: a0412235; Lib Reference: IEC_Caution
footprint IEC_Caution_Large
footprint IEC_Caution_Small
footprint IEC_Caution_Medium

## CMP-0074837-2
designator LOGO?, comment CAUTION HOT SURFACE  (no BOM)
IEC 61010-1 Hot Surface Warning; Manufacturer: Texas Instruments; SymbolCreator: a0412235; Lib Reference: IEC_HotSurface; CompType: IC; AEC Category: Q200
footprint IEC_HotSurface_Large
footprint IEC_HotSurface_Small
footprint IEC_HotSurface_Medium

## CMP-0074838-1
designator Logo?, comment Texas Instruments  (no BOM)
Texas Instrument Corporate Signature; SymbolCreator: a0412235; Lib Reference: TI_Logo; Library Reference: Logo
footprint TI_Horizontal_Overlay_Medium
footprint TI_Horizontal_Overlay_Small
footprint TI_Stacked_SolderMask_Small
footprint TI_Stacked_SolderMask_Small_Vertical
footprint TI_Symbol_Overlay_Medium
footprint TI_Symbol_Overlay_Small
footprint TI_Symbol_SolderMask_Medium
footprint TI_Symbol_SolderMask_Small
footprint TI_Horizontal_SolderMask_Medium
footprint TI_Horizontal_SolderMask_Small
footprint TI_Stacked_Overlay_Medium
footprint TI_Stacked_Overlay_Medium_Vertical
footprint TI_Stacked_Overlay_Small
footprint TI_Stacked_Overlay_Small_Vertical
footprint TI_Stacked_SolderMask_Medium
footprint TI_Stacked_SolderMask_Medium_Vertical

## CMP-0074844-1
designator Logo?, comment CE Mark  (no BOM)
SymbolCreator: a0412235
footprint CE_Mark_5mm (Minimum text height for CE Mark)
footprint CE_Mark_10mm (Double the minimum text height for CE Mark)

## CMP-0074847-1
designator Logo?, comment FCC disclaimer  (no BOM)
FCC_disclaimer; Library Reference: Logo
footprint FCC_disclaimer
footprint FCC_disclaimer_stacked

## CMP-0075110-1
designator TP?, comment Jumper_2p  (value not drawn)
1mm Uninsulated Shorting Plug, 10.16mm spacing, TH; Manufacturer: Harwin; PartNumber: D3082-05; CompType: Jumper Wire; CNHeader: False; Green_Lifecycle: Active; Green_REACh: Passed
footprint Harwin_D3082-05 (Shorting Plug, 10.16mm spacing, TH)
pins: 1, 2

## CMP-0075483-1
designator J?, comment HTSW-102-07-G-S  (value not drawn)
Header, 100mil, 2x1, Gold, TH; Manufacturer: Samtec; Green_REACh: Passed; CT: False; Green_Lifecycle: Active; CNHeader: True
footprint Samtec_HTSW-102-07-G-S (Samtec 100mil, 1x2, 230 mil above insulator)
pins: 1, 2
1 alternate drawing of the same symbol

## CMP-0077181-1
designator FID?, comment Fiducial  (value not drawn)
Fiducial mark.  There is nothing to buy or mount.
footprint Fiducial10-30
footprint Fiducial15-30
footprint Fiducial10-20
footprint Fiducial20-40
footprint Fiducial6.4-20

## CMP-0077236-1
designator ZZ?, comment These assemblies are ESD sensitive, ESD precautions shall be observed.  (no BOM)
CompType: AssemblyNote
footprint AssemblyNote (Assembly Note)

## CMP-0077237-1
designator ZZ?, comment These assemblies must be clean and free from flux and all contaminants. Use of no clean flux is not acceptable.  (no BOM)
CompType: AssemblyNote
footprint AssemblyNote (Assembly Note)

## CMP-0077238-1
designator ZZ?, comment These assemblies must comply with workmanship standards IPC-A-610 Class 2, unless otherwise specified.  (no BOM)
CompType: AssemblyNote
footprint AssemblyNote (Assembly Note)

## CMP-0077592-3
designator D?, comment value 2.7V  (hidden comment: MMSZ4682-E3-08)
Diode, Zener, 2.7 V, 500 mW, SOD-123; Manufacturer: Vishay-Semiconductor; AEC Category: Q101; AEC Qualified: N; SizeAreaWB_mm2: 13.095; SizeY_mm: 1.7; SizeX_mm: 3.85; Value1: 0.5W; SizeArea_mm2: 6.545; SizeZ_mm: 1.35; RJA_CperW: 340; Power_W: 500mW
footprint SOD-123 (On Semi recommended land pattern)
pins: 1 K, 2 A

## CMP-0078153-1
designator C?, comment PackageReference: 0805  VDC_V: 10V  ValueDisplayed: 22µF  (hidden comment: 885012107011)
CAP, CERM, 22 µF, 10 V,+/- 20%, X5R, 0805; Manufacturer: Wurth Elektronik; TaMin_C: -55°C; Polarized: N; SizeAreaWB_mm2: 6.75; U/M: EA; Value: 22uF; TaMax_C: 85°C; SizeZ_mm: 1.5; SizeX_mm: 2; SizeY_mm: 1.25; SizeArea_mm2: 2.5; CompType: Capacitor; AEC Category: Q200
footprint 0805_150 (0805 / 1.5 mm height)
pins: 1, 2

## CMP-0079993-1
designator C?, comment 885012206114  (value not drawn)
CAP, CERM, 0.01 µF, 100 V,+/- 10%, X7R, 0603; Manufacturer: Wurth Elektronik; TaMin_C: -55°C; Polarized: N; SizeAreaWB_mm2: 4.68; U/M: EA; Value: 0.01uF; TaMax_C: 105°C; SizeZ_mm: 1; SizeX_mm: 1.6; SizeY_mm: 0.8; Cap_Case: 0603; Value2: 100V; SizeArea_mm2: 1.28; CompType: Capacitor; Cap_F: 10nF; AEC Category: Q200; ValueDisplayed: 0.01µF
footprint 0603 (0603 from SM-752 data)
footprint 0603M (0603 from SM-752 data)
footprint 0603L (0603 from SM-752 data)
footprint 0603_HV (Ernesto recommended land pattern.  26 mil between pads.)
footprint 0603S
pins: 1, 2

## CMP-0082533-1
designator R?, comment ValueDisplayed: 4.99k  (hidden comment: CRCW06034K99FKEAC)
RES, 4.99 k, 1%, 0.1 W, 0603; Manufacturer: Vishay-Dale; CompType: Resistor; Value: 4.99k; Value_Code: 4k99; Power_W: 100mW; Value2: 0.1W; VDC_V: 75V; TempCo: 100 ppm/C; EIA_Code: E96; AEC Category: Q200; AEC Qualified: N; SizeAreaWB_mm2: 4.68; SizeX_mm: 1.6; SizeY_mm: 0.8; SizeZ_mm: 1; SizeArea_mm2: 1.28
footprint 0603 (0603 from SM-752 data)
footprint 0603M (0603 from SM-752 data)
footprint 0603L (0603 from SM-752 data)
footprint 0603_HV (Ernesto recommended land pattern.  26 mil between pads.)
footprint 0603S
pins: 1, 2

## CMP-0084439-1
designator F?, comment 0466003.NR
Fuse, 3 A, 32VAC/VDC, SMD; Manufacturer: Littelfuse; VAC_V: 32V; Rtyp_Ohm: 0.019; Interrupt_AC: 50A; MeltingTyp: 0.576; SizeX_mm: 3.2; Fuse Technology: Board Mount; Irating_A: 3A; SizeAreaWB_mm2: 10.92; TaMin_C: -55°C; Fuse Speed: Fast; SizeArea_mm2: 5.12; SizeY_mm: 1.6; SizeZ_mm: 1.35; TaMax_C: 90°C
footprint 1206 (1206 from SM-752 data)
footprint 1206M (1206 from SM-752 data)
footprint 1206L (1206 from SM-752 data)
pins: 1, 2

## CMP-0085483-1
designator Y?, comment CSTNR4M00GH5L000R0  (value not drawn)
Oscillator, 4 MHz, 700 ppm, 39 pF, SMD; Manufacturer: MuRata; SizeArea_mm2: 9; Load Capacitance: 39 pF; SizeZ_mm: 1.2; AEC Category: Q200; Frequency Tolerance: 700 ppm; SizeX_mm: 4.5; SizeAreaWB_mm2: 16.5; TaMax_C: 85°C; TaMin_C: -20°C; SizeY_mm: 2; AEC Qualified: N; Frequency_Fixed: 4MHz
footprint MuRata_CSTNR (SMD, 3-Leads, Body 4.5x2mm, Pitch 1.5mm)
pins: 1 In, 2 GND, 3 Out

## CMP-0086014-1
designator J?, comment 61301421121
Header, 2.54mm, 7x2, Gold, TH; Manufacturer: Wurth Elektronik; Pitch_mm: 2.54; Voltage_V: 250V; Shrouded: N; Gender: Male; Current_A: 3A; Cert_UL: Y; Row_Count: 2
footprint Wurth_61301421121 (Header, 2.54mm, 7x2, TH)
pins: 1, 2, 3, 4, 5, 6, 7, 8, 9, 10, 11, 12, 13, 14
1 alternate drawing of the same symbol

## CMP-0090362-1
designator C?, comment 885012205018  (value not drawn)
0.1µF ±10% 10V Ceramic Capacitor X7R 0402 (1005 Metric); Manufacturer: Wurth Electronics; AEC Qualified: No; Value: 100nF; SizeZ_mm: 0.55mm; ValueDisplayed: 100000pF; TempCo: 15%
footprint FP-885012205018_0402-MFG
footprint FP-885012205018_0402-IPC_C
footprint FP-885012205018_0402-IPC_B
footprint FP-885012205018_0402-IPC_A
pins: 1, 2

## CMP-0093233-2
designator J?, comment 691250610002  (value not drawn)
2 Position Wire to Board Terminal Block Horizontal with Board 0.250" (6.35mm) Through Hole; Manufacturer: Wurth Electronics; Current_A: 32A; Conn Gender: Female; Row_Count: 1; ContactFinish: Zinc; SizeZ_mm: 21.6mm; Max Wire Gauge: 10; Min Wire Gauge: 30; Voltage_V: 450V; AEC Qualified: No; Is Female: yes
footprint FP-691250610002_CONN_TERM_BLOCK2-MFG
pins: 1, 2

## CMP-0094458-1
designator C?, comment ValueDisplayed: 10uF  VDC_V: 25V  (hidden comment: ZRB18AR61E106ME01L)
10µF ±20% 25V Ceramic Capacitor X5R 0603 (1608 Metric); Manufacturer: Murata Electronics; SizeZ_mm: 1.2mm; AEC Qualified: No
footprint FP-ZRB18AR61E106ME01L_0603-MFG
pins: 1, 2

## CMP-0095262-1
designator R?, comment SG73S1JTTD101J  (value not drawn)
100 Ohms ±5% 0.2W, 1/5W Chip Resistor 0603 (1608 Metric) Automotive AEC-Q200, Moisture Resistant, Pulse Withstanding Thick Film; Manufacturer: KOA Speer; AEC Qualified: Yes; Value: 100; AEC Grade: Grade 0; VDC_V: 150V; TaMax_C: +70°C; TempCo: 100ppm/°C; Power_W: 200mW; SizeZ_mm: 0.55mm
footprint FP-SG73S1JTTD101J_0603-MFG
footprint FP-SG73S1JTTD101J_0603-IPC_C
footprint FP-SG73S1JTTD101J_0603-IPC_B
footprint FP-SG73S1JTTD101J_0603-IPC_A
pins: 1, 2

## CMP-0097305-1
designator C?, comment ValueDisplayed: 4.7uF  VDC_V: 10V  (hidden comment: 885012106012)
4.7 µF ±20% 10V Ceramic Capacitor X5R 0603 (1608 Metric); Manufacturer: Wurth Electronics; Cap_F: 4.7µF; Value: 4.7µF; AEC Qualified: No; SizeZ_mm: 0.87mm; TempCo: 15%
footprint FP-885012106012_0603-MFG
footprint FP-885012106012_0603-IPC_C
footprint FP-885012106012_0603-IPC_B
footprint FP-885012106012_0603-IPC_A
pins: 1, 2

## CMP-0097306-1
designator C?, comment ValueDisplayed: 33pF  VDC_V: 50V  (hidden comment: 885012005058)
33 pF ±5% 50V Ceramic Capacitor C0G, NP0 0402 (1005 Metric); Manufacturer: Wurth Electronics; AEC Qualified: No; Value: 33pF; TempCo: 30ppm/°C; SizeZ_mm: 0.55mm
footprint FP-885012005058_0402-MFG
footprint FP-885012005058_0402-IPC_C
footprint FP-885012005058_0402-IPC_B
footprint FP-885012005058_0402-IPC_A
pins: 1, 2

## CMP-0097311-1
designator C?, comment ValueDisplayed: 1nF  VDC_V: 100V  (hidden comment: 885012006085)
1000 pF ±5% 100V Ceramic Capacitor C0G, NP0 0603 (1608 Metric); Manufacturer: Wurth Electronics; TempCo: 30ppm/°C; SizeZ_mm: 0.87mm; AEC Qualified: No; Value: 1nF
footprint FP-885012006085_0603-MFG
footprint FP-885012006085_0603-IPC_C
footprint FP-885012006085_0603-IPC_B
footprint FP-885012006085_0603-IPC_A
pins: 1, 2

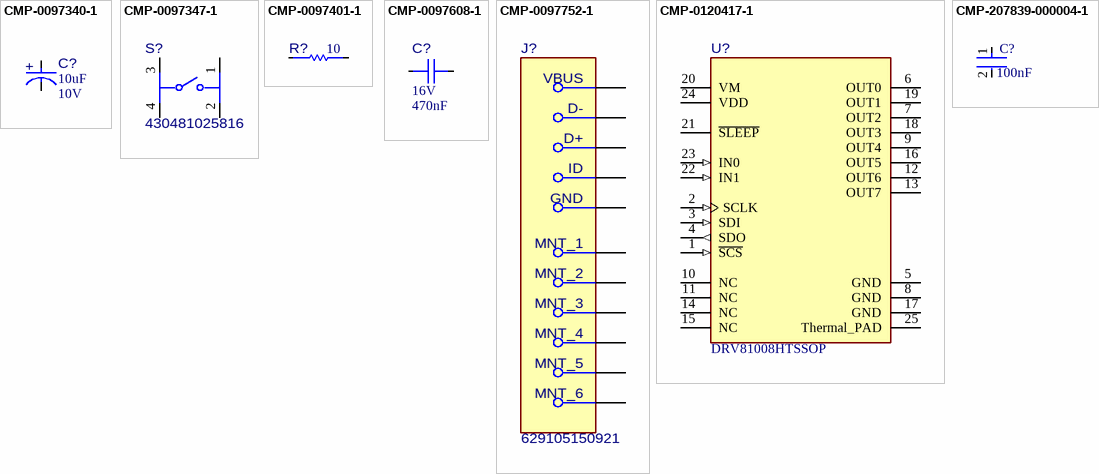
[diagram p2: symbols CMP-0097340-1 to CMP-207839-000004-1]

## CMP-0097340-1
designator C?, comment ValueDisplayed: 10uF  VDC_V: 10V  (hidden comment: 875105240001)
Alum. Polymer Cap 10µF 10V 5.5mmV-Chip WCAP-PSLP Series Lifetime 2000h +105°C; Manufacturer: Wurth Electronics; Life: 2000Hours; Dissipation Factor: 8%; Esr: 45m; IRMS_A: 1.2A; Tolerance_%: 20%; AEC Qualified: No; SizeZ_mm: 5.5mm; Leakage Current: 300uA
footprint FP-875105240001_SMT_CAP_4MM3_4MM3-MFG
pins: 1 CATHODE, 2 ANODE

## CMP-0097347-1
designator S?, comment 430481025816
Tactile Switch SPST-NO Top Actuated Surface Mount; Manufacturer: Wurth Electronics; VDC_V: 12V; Electromechanical Life: 1000000Cycles; SizeZ_mm: 2.7mm; Coil Resistance_ohm: 100mΩ; Operating Force: 160gf; AEC Qualified: No; Contact Current Rating: 50mA
footprint FP-430481025816_SMT_SW_6MM2_6MM2-MFG
pins: 1, 2, 3, 4

## CMP-0097401-1
designator R?, comment value 10  (hidden comment: 560050310009)
Thick Film Resistors 0402 10Ω ±1% 0.125W; Manufacturer: Wurth Electronics; TempCo: 100ppm/°C; VDC_V: 1.118V; Power_W: 125mW; AEC Qualified: No; SizeZ_mm: 0.4mm
footprint FP-560050310009_0402-MFG
footprint FP-560050310009_0402-IPC_C
footprint FP-560050310009_0402-IPC_B
footprint FP-560050310009_0402-IPC_A
pins: 1, 2

## CMP-0097608-1
designator C?, comment VDC_V: 16V  Cap_F: 470nF  (hidden comment: 885012206050)
0.47 µF ±10% 16V Ceramic Capacitor X7R 0603 (1608 Metric); Manufacturer: Wurth Electronics; AEC Qualified: No; Value: 470nF; TempCo: 15%; SizeZ_mm: 0.87mm
footprint FP-885012206050_0603-MFG
footprint FP-885012206050_0603-IPC_C
footprint FP-885012206050_0603-IPC_B
footprint FP-885012206050_0603-IPC_A
pins: 1, 2

## CMP-0097752-1
designator J?, comment 629105150921
Conn Micro USB 2.0 Type AB RCP 5 POS 0.65mm Solder RA SMD 5 Terminal 1 Port T/R; Manufacturer: Wurth Electronics; Shrouded: true; Voltage_V: 30V; Usb Standard: USB 2.0; Current_A: 1A; ContactFinish: Gold; SizeZ_mm: 3.2mm; Is Female: yes; Conn Orientation: Horizontal; AEC Qualified: No
footprint FP-629105150921_CONN_PTH_USB_8MM0_5MM6-MFG
pins: 1 VBUS, 2 D-, 3 D+, 4 ID, 5 GND (power), 6 MNT_1, 7 MNT_2, 8 MNT_3, 9 MNT_4, 10 MNT_5, 11 MNT_6

## CMP-0120417-1
designator U?, comment DRV81008HTSSOP
8-channel Configurable Low-side and High-side Driver for Automotive Relay, Lighting and Motor Control; Manufacturer: Texas Instruments; SizeZ_mm: 1.2mm; AEC Qualified: No; Max Supply Voltage: 40V; Min Supply Voltage: 3V; Number Of Outputs: 8; Standoff Height: 0.05mm; TaMax_C: +125°C; TaMin_C: -40°C; TJmax_C: +150°C
footprint PWP0024T-MFG
footprint PWP0024T-IPC_C
footprint PWP0024T-IPC_B
footprint PWP0024T-IPC_A
pins: 1 ~{SCS} (in), 2 SCLK (in), 3 SDI (in), 4 SDO (out), 5 GND (power), 6 OUT0, 7 OUT2, 8 GND (power), 9 OUT4, 10 NC, 11 NC, 12 OUT6, 13 OUT7, 14 NC, 15 NC, 16 OUT5, 17 GND (power), 18 OUT3, 19 OUT1, 20 VM (power), 21 ~{SLEEP}, 22 IN1 (in), 23 IN0 (in), 24 VDD (power), 25 Thermal_PAD (power)

## CMP-207839-000004-1
designator C?, comment value 100nF  (hidden comment: 885012206095)
CAP CER 0.1UF 50V X7R 0603; Tolerance: 10%
footprint FP-885012206095-MFG
footprint FP-885012206095-IPC_C
footprint FP-885012206095-IPC_B
footprint FP-885012206095-IPC_A
pins: 1, 2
